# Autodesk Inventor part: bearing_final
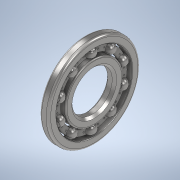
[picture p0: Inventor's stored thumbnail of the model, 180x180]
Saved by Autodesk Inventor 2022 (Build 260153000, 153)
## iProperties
Created: 2021-06
Part Number: bearing_final
Material: Generic
Document SubType Name: Modeling
Designer: Chimms
Density: 1 g/cm^3
Appearance: Default
Author: Chimms
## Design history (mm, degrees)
derived "ball bearing.iam" dims "d0" = 1.11111
body "Solid1"
node "ball bearingPart1.ipt:1" dims "d0" = 1.11111
